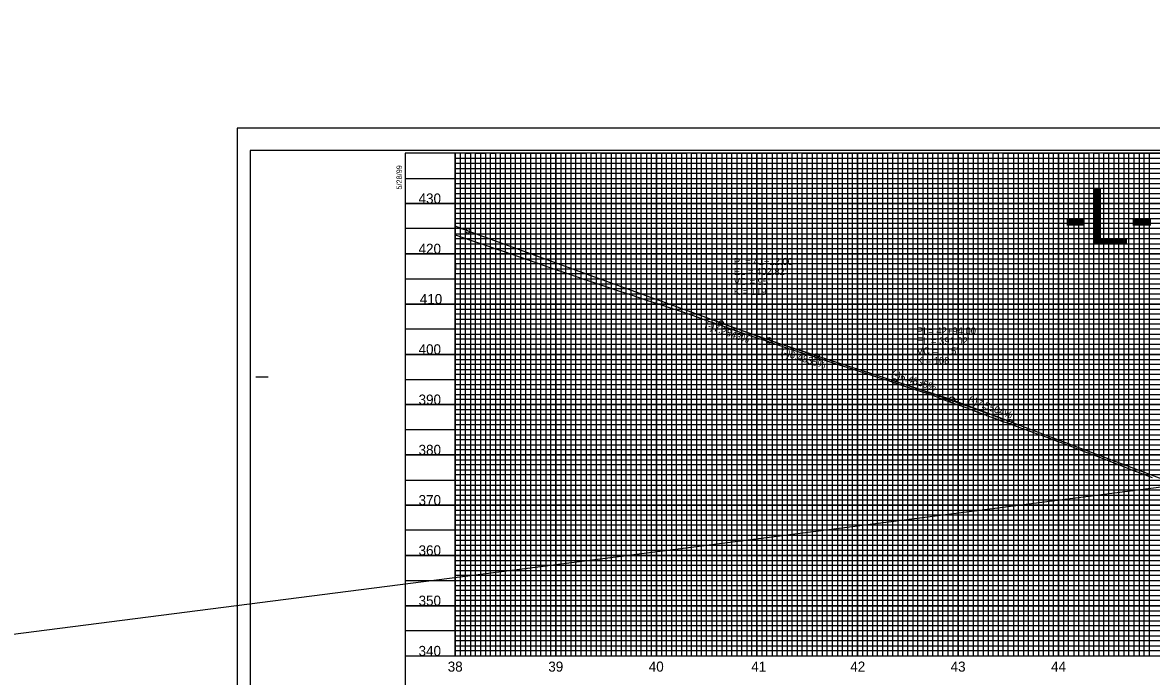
# Model space of a CAD drawing. Extents: x 571503 to 593215, y -77195 to -51828.
# Drawn here: x 583403 to 584526, y -53129 to -52479 of the extents above; entities that cross this region are included whole.
import ezdxf

# ---------------------------------------------------------------- set-up
doc = ezdxf.new("R2010")
doc.units = 0
for name, color, linetype in [('Default', 7, 'Continuous'), ('Exist Vertical Profile Ground Line', 7, 'Continuous'), ('Exist Vertical Profile Horizontal Axis Label Major', 7, 'Continuous'), ('Exist Vertical Profile Vertical Axis Label', 7, 'Continuous'), ('Prop PFL Text', 7, 'Continuous'), ('Prop Vertical Profile Curve Label', 7, 'Continuous'), ('Prop Vertical Profile Grade', 7, 'Continuous'), ('Prop Vertical Profile Grade Label', 7, 'Continuous'), ('Prop VPI Label', 7, 'Continuous'), ('Sheet Clip Boundary CELL', 7, 'Continuous'), ('Sheet DOT Grid CELL', 7, 'Continuous'), ('Sheet Plot Border Inside CELL', 7, 'Continuous'), ('Sheet Plot Border Outside CELL', 7, 'Continuous'), ('Sheet Profile CELL', 7, 'Continuous'), ('Sheet Profile Grid Major CELL', 7, 'Continuous'), ('Sheet Profile Grid Middle CELL', 7, 'Continuous'), ('Sheet Profile Grid Minor CELL', 7, 'Continuous')]:
    doc.layers.add(name, color=color, linetype=linetype)

msp = doc.modelspace()

# ---------------------------------------------------------------- linework, layer by layer
at = {"layer": 'Exist Vertical Profile Ground Line'}
for points in [[(583833.2, -52689.7), (583848.4, -52695), (583865.3, -52700.8), (583873.4, -52703.6), (583881.7, -52706.5), (583897, -52711.8), (583913.3, -52717.4), (583921.5, -52720.3), (583926.1, -52721.9), (583941.7, -52727.2), (583958.3, -52733), (583960.7, -52733.8), (583964.9, -52735.2), (583980.1, -52740.3), (583996.6, -52745.8), (584007.2, -52749.3), (584023.5, -52754.9), (584039.2, -52759.8), (584046, -52762.2), (584054.1, -52764.8), (584069.9, -52770.2), (584086.1, -52775.9), (584093.5, -52778.5), (584101, -52781.1), (584116.4, -52786.5), (584133, -52792.2), (584142.6, -52795.4), (584151.1, -52798.3), (584166.5, -52803.4), (584183.1, -52808.7), (584189.9, -52810.9), (584198.7, -52813.8), (584214.1, -52818.8), (584227.8, -52823.2), (584229.5, -52823.7), (584238.8, -52826.7), (584241, -52827.4), (584248, -52829.7), (584255, -52832), (584257.3, -52832.8), (584266.6, -52835.8), (584267.7, -52836.2), (584275.9, -52838.9), (584280.9, -52840.6), (584285.1, -52842), (584285.7, -52842.2), (584294.4, -52845.1), (584303.7, -52848.1), (584305.9, -52848.8), (584313, -52851.4), (584315.1, -52852.2), (584322.2, -52854.9)], [(584322.2, -52854.9), (584329.3, -52857.5), (584331.5, -52858.3), (584333.4, -52859), (584340.8, -52861.7), (584350.1, -52865.2), (584359.3, -52868.7), (584360.4, -52869), (584361, -52869.3), (584361.5, -52869.5), (584368.6, -52872), (584377.9, -52875.4), (584383.2, -52877.3), (584383.7, -52877.4), (584387.2, -52878.7), (584396.4, -52882), (584405.7, -52885.4), (584414.6, -52888.6), (584415, -52888.7), (584415.8, -52889), (584424.3, -52892.2), (584433.5, -52895.7), (584435.7, -52896.5), (584436.3, -52896.7), (584442.8, -52899.2), (584452.1, -52902.7), (584461.4, -52906.2), (584467.5, -52908.5), (584468, -52908.7), (584470.6, -52909.7), (584479.9, -52913.3), (584489.2, -52916.9), (584489.2, -52916.9), (584489.3, -52916.9), (584498.5, -52920.5), (584507.7, -52924.1), (584516.7, -52927.5), (584517, -52927.7), (584521.1, -52929.2), (584521.1, -52929.2), (584526.3, -52931.2)]]:
    msp.add_lwpolyline(points, dxfattribs=at)
at = {"layer": 'Prop PFL Text'}
msp.add_line((571799.6, -54572.4), (593215.4, -51828.4), dxfattribs=at)
at = {"layer": 'Prop Vertical Profile Curve Label'}
for centre in [(583845.7, -52685.8), (584097.7, -52777.5), (584192.7, -52810.2), (584269.7, -52835.2), (584384.7, -52875.6)]:
    msp.add_circle(centre, 2.25, dxfattribs=at)
at = {"layer": 'Prop Vertical Profile Grade'}
for p, q in [((583845.7, -52685.8), (584097.7, -52777.5)), ((584192.7, -52810.2), (584269.7, -52835.2)), ((584384.7, -52875.6), (584642.2, -52972.8))]:
    msp.add_line(p, q, dxfattribs=at)
for points in [[(583833.2, -52681.3), (583837, -52682.6), (583845.7, -52685.8)], [(584097.7, -52777.5), (584099.6, -52778.2), (584101.5, -52778.9), (584103.4, -52779.6), (584105.3, -52780.3), (584107.2, -52781), (584109.1, -52781.7), (584111, -52782.4), (584112.9, -52783), (584114.8, -52783.7), (584116.7, -52784.4), (584118.6, -52785.1), (584120.5, -52785.7), (584122.4, -52786.4), (584124.3, -52787.1), (584126.2, -52787.8), (584128.1, -52788.4), (584130, -52789.1), (584131.9, -52789.8), (584133.8, -52790.4), (584135.7, -52791.1), (584137.6, -52791.7), (584139.5, -52792.4), (584141.4, -52793.1), (584143.3, -52793.7), (584145.2, -52794.4), (584147.1, -52795), (584149, -52795.7), (584150.9, -52796.3), (584152.8, -52797), (584154.7, -52797.6), (584156.6, -52798.3), (584158.5, -52798.9), (584160.4, -52799.6), (584162.3, -52800.2), (584164.2, -52800.8), (584166.1, -52801.5), (584168, -52802.1), (584169.9, -52802.7), (584171.8, -52803.4), (584173.7, -52804), (584175.6, -52804.6), (584177.5, -52805.3), (584179.4, -52805.9), (584181.3, -52806.5), (584183.2, -52807.1), (584185.1, -52807.8), (584187, -52808.4), (584188.9, -52809), (584190.8, -52809.6), (584192.7, -52810.2)], [(584269.7, -52835.2), (584272, -52836), (584274.3, -52836.7), (584276.6, -52837.5), (584278.9, -52838.2), (584281.2, -52839), (584283.5, -52839.7), (584285.8, -52840.5), (584288.1, -52841.3), (584290.4, -52842), (584292.7, -52842.8), (584295, -52843.6), (584297.3, -52844.3), (584299.6, -52845.1), (584301.9, -52845.9), (584304.2, -52846.7), (584306.5, -52847.5), (584308.8, -52848.2), (584311.1, -52849), (584313.4, -52849.8), (584315.7, -52850.6), (584318, -52851.4), (584320.3, -52852.2), (584322.6, -52853), (584324.9, -52853.8), (584327.2, -52854.6), (584329.5, -52855.4), (584331.8, -52856.2), (584334.1, -52857), (584336.4, -52857.9), (584338.7, -52858.7), (584341, -52859.5), (584343.3, -52860.3), (584345.6, -52861.2), (584347.9, -52862), (584350.2, -52862.8), (584352.5, -52863.6), (584354.8, -52864.5), (584357.1, -52865.3), (584359.4, -52866.2), (584361.7, -52867), (584364, -52867.8), (584366.3, -52868.7), (584368.6, -52869.5), (584370.9, -52870.4), (584373.2, -52871.2), (584375.5, -52872.1), (584377.8, -52873), (584380.1, -52873.8), (584382.4, -52874.7), (584384.7, -52875.6)]]:
    msp.add_spline(points, degree=3, dxfattribs=at)
at = {"layer": 'Prop VPI Label'}
for p, q in [((583845.7, -52685.8), (583833.2, -52681.2)), ((584097.7, -52777.5), (584142.6, -52793.9)), ((584192.7, -52810.2), (584147.8, -52795.7)), ((584269.7, -52835.2), (584324.6, -52853)), ((584384.7, -52875.6), (584329.8, -52854.8))]:
    msp.add_line(p, q, dxfattribs=at)
for centre in [(584145.2, -52794.8), (584327.2, -52853.8)]:
    msp.add_circle(centre, 2.75, dxfattribs=at)
at = {"layer": 'Sheet Clip Boundary CELL'}
msp.add_lwpolyline([(583833.2, -52608.7), (583833.2, -53108.7), (585233.2, -53108.7), (585233.2, -52746.2), (585083.2, -52746.2), (585083.2, -52608.7)], close=True, dxfattribs=at)
at = {"layer": 'Sheet DOT Grid CELL'}
for p, q in [((583833.2, -53108.7), (583833.2, -52608.7)), ((583833.2, -53108.7), (583833.2, -52608.7)), ((583883.2, -53108.7), (583883.2, -52608.7)), ((583883.2, -53108.7), (583883.2, -52608.7)), ((583933.2, -53108.7), (583933.2, -52608.7)), ((583933.2, -53108.7), (583933.2, -52608.7)), ((583983.2, -53108.7), (583983.2, -52608.7)), ((583983.2, -53108.7), (583983.2, -52608.7)), ((584033.2, -53108.7), (584033.2, -52608.7)), ((584033.2, -53108.7), (584033.2, -52608.7)), ((584083.2, -53108.7), (584083.2, -52608.7)), ((584083.2, -53108.7), (584083.2, -52608.7)), ((584133.2, -53108.7), (584133.2, -52608.7)), ((584133.2, -53108.7), (584133.2, -52608.7)), ((584183.2, -53108.7), (584183.2, -52608.7)), ((584183.2, -53108.7), (584183.2, -52608.7)), ((584233.2, -53108.7), (584233.2, -52608.7)), ((584233.2, -53108.7), (584233.2, -52608.7)), ((584283.2, -53108.7), (584283.2, -52608.7)), ((584283.2, -53108.7), (584283.2, -52608.7)), ((584333.2, -53108.7), (584333.2, -52608.7)), ((584333.2, -53108.7), (584333.2, -52608.7)), ((584383.2, -53108.7), (584383.2, -52608.7)), ((584383.2, -53108.7), (584383.2, -52608.7)), ((584433.2, -53108.7), (584433.2, -52608.7)), ((584433.2, -53108.7), (584433.2, -52608.7)), ((584483.2, -53108.7), (584483.2, -52608.7)), ((584483.2, -53108.7), (584483.2, -52608.7)), ((583783.2, -52658.7), (585083.2, -52658.7)), ((585083.2, -52658.7), (583783.2, -52658.7)), ((583783.2, -52708.7), (585083.2, -52708.7)), ((585083.2, -52708.7), (583783.2, -52708.7)), ((583783.2, -52758.7), (585283.2, -52758.7)), ((585283.2, -52758.7), (583783.2, -52758.7)), ((583783.2, -52808.7), (585283.2, -52808.7)), ((585283.2, -52808.7), (583783.2, -52808.7)), ((583783.2, -52858.7), (585283.2, -52858.7)), ((585283.2, -52858.7), (583783.2, -52858.7)), ((583783.2, -52908.7), (585283.2, -52908.7)), ((585283.2, -52908.7), (583783.2, -52908.7)), ((583783.2, -52958.7), (585283.2, -52958.7)), ((585283.2, -52958.7), (583783.2, -52958.7)), ((583783.2, -53008.7), (585283.2, -53008.7)), ((585283.2, -53008.7), (583783.2, -53008.7)), ((583783.2, -53058.7), (585283.2, -53058.7)), ((585283.2, -53058.7), (583783.2, -53058.7))]:
    msp.add_line(p, q, dxfattribs=at)
at = {"layer": 'Sheet Plot Border Inside CELL'}
msp.add_lwpolyline([(583629.2, -53661.2), (585295.7, -53661.2), (585295.7, -52606.1), (583629.2, -52606.1)], close=True, dxfattribs=at)
at = {"layer": 'Sheet Plot Border Outside CELL'}
msp.add_lwpolyline([(583616.2, -53683.7), (585300.2, -53683.7), (585300.2, -52583.7), (583616.2, -52583.7)], close=True, dxfattribs=at)
at = {"layer": 'Sheet Profile CELL'}
for p, q in [((585300.2, -52583.7), (583616.2, -52583.7)), ((583616.2, -52583.7), (583616.2, -53683.7)), ((583634.7, -52831.2), (583647.2, -52831.2)), ((583783.2, -53108.7), (585283.2, -53108.7))]:
    msp.add_line(p, q, dxfattribs=at)
msp.add_lwpolyline([(585283.2, -52608.7), (583783.2, -52608.7), (583783.2, -53658.7), (585283.2, -53658.7)], close=True, dxfattribs=at)
at = {"layer": 'Sheet Profile Grid Major CELL'}
for points in [[(583833.2, -52608.7), (583833.2, -53108.7), (583883.2, -53108.7), (583883.2, -52608.7), (583933.2, -52608.7), (583933.2, -53108.7), (583983.2, -53108.7), (583983.2, -52608.7), (584033.2, -52608.7), (584033.2, -53108.7), (584083.2, -53108.7), (584083.2, -52608.7), (584133.2, -52608.7), (584133.2, -53108.7), (584183.2, -53108.7), (584183.2, -52608.7), (584233.2, -52608.7), (584233.2, -53108.7), (584283.2, -53108.7), (584283.2, -52608.7), (584333.2, -52608.7), (584333.2, -53108.7), (584383.2, -53108.7), (584383.2, -52608.7), (584433.2, -52608.7), (584433.2, -53108.7), (584483.2, -53108.7), (584483.2, -52608.7), (584533.2, -52608.7)], [(583783.2, -52658.7), (585083.2, -52658.7)], [(585083.2, -52708.7), (583783.2, -52708.7), (583783.2, -52758.7), (585283.2, -52758.7)], [(585283.2, -52808.7), (583783.2, -52808.7), (583783.2, -52858.7), (585283.2, -52858.7)], [(585283.2, -52908.7), (583783.2, -52908.7), (583783.2, -52958.7), (585283.2, -52958.7)], [(585283.2, -53008.7), (583783.2, -53008.7), (583783.2, -53008.7), (583783.2, -53058.7), (585283.2, -53058.7)]]:
    msp.add_lwpolyline(points, dxfattribs=at)
at = {"layer": 'Sheet Profile Grid Middle CELL'}
msp.add_line((583783.2, -52633.7), (585083.2, -52633.7), dxfattribs=at)
for points in [[(583858.2, -52608.7), (583858.2, -53108.7), (583908.2, -53108.7), (583908.2, -52608.7), (583958.2, -52608.7), (583958.2, -53108.7), (584008.2, -53108.7), (584008.2, -52608.7), (584058.2, -52608.7), (584058.2, -53108.7), (584108.2, -53108.7), (584108.2, -52608.7), (584158.2, -52608.7), (584158.2, -53108.7), (584208.2, -53108.7), (584208.2, -52608.7), (584258.2, -52608.7), (584258.2, -53108.7), (584308.2, -53108.7), (584308.2, -52608.7), (584358.2, -52608.7), (584358.2, -53108.7), (584408.2, -53108.7), (584408.2, -53108.7), (584408.2, -52608.7), (584458.2, -52608.7), (584458.2, -53108.7), (584508.2, -53108.7), (584508.2, -52608.7), (584558.2, -52608.7)], [(585083.2, -52683.7), (583783.2, -52683.7), (583783.2, -52733.7), (585083.2, -52733.7)], [(585283.2, -52783.7), (583783.2, -52783.7), (583783.2, -52833.7), (585108.2, -52833.7)], [(585283.2, -52883.7), (583783.2, -52883.7), (583783.2, -52933.7), (585283.2, -52933.7)], [(585283.2, -52983.7), (583783.2, -52983.7), (583783.2, -53033.7), (585283.2, -53033.7)], [(585283.2, -53083.7), (583783.2, -53083.7)]]:
    msp.add_lwpolyline(points, dxfattribs=at)
at = {"layer": 'Sheet Profile Grid Minor CELL'}
for p, q in [((583833.2, -52613.7), (585083.2, -52613.7)), ((583833.2, -52618.7), (583833.2, -52618.7)), ((585083.2, -52618.7), (583833.2, -52619)), ((583833.2, -52623.7), (585083.2, -52623.7)), ((585083.2, -52743.7), (583833.2, -52743.7)), ((585233.2, -52748.7), (583833.2, -52748.7)), ((585233.2, -52753.7), (583833.2, -52753.7)), ((583833.2, -52763.7), (585233.2, -52763.7)), ((585233.2, -52768.7), (583833.2, -52768.7)), ((583833.2, -52773.7), (585233.2, -52773.7)), ((585233.2, -52793.7), (583833.2, -52793.7)), ((583833.2, -52798.7), (585233.2, -52798.7)), ((585233.2, -52818.7), (583833.2, -52818.7)), ((583833.2, -52823.7), (585233.2, -52823.7)), ((585233.2, -52843.7), (583833.2, -52843.7)), ((583833.2, -52848.7), (585233.2, -52848.7)), ((585233.2, -52853.7), (583833.2, -52853.7)), ((583833.2, -52863.7), (585233.2, -52863.7)), ((585233.2, -52868.7), (583833.2, -52868.7)), ((583833.2, -52873.7), (585233.2, -52873.7)), ((585233.2, -52878.7), (583833.2, -52878.7)), ((583833.2, -52888.7), (585233.2, -52888.7)), ((585233.2, -52893.7), (583833.2, -52893.7)), ((583833.2, -52898.7), (585233.2, -52898.7)), ((585233.2, -52903.7), (583833.2, -52903.7)), ((583833.2, -52913.7), (585233.2, -52913.7)), ((585233.2, -52918.7), (583833.2, -52918.7)), ((583833.2, -52923.7), (585233.2, -52923.7)), ((585233.2, -52928.7), (583833.2, -52928.7)), ((583833.2, -52938.7), (585233.2, -52938.7)), ((585233.2, -52943.7), (583833.2, -52943.7)), ((583833.2, -52948.7), (585233.2, -52948.7)), ((585233.2, -52953.7), (583833.2, -52953.7)), ((583833.2, -52963.7), (585233.2, -52963.7)), ((585233.2, -52968.7), (583833.2, -52968.7)), ((583833.2, -52973.7), (585233.2, -52973.7)), ((585233.2, -52978.7), (583833.2, -52978.7)), ((583833.2, -52988.7), (585233.2, -52988.7)), ((585233.2, -52993.7), (583833.2, -52993.7)), ((585233.2, -52998.7), (583833.2, -52998.7)), ((585233.2, -53003.7), (583833.2, -53003.7)), ((583833.2, -53013.7), (585233.2, -53013.7)), ((585233.2, -53018.7), (583833.2, -53018.7)), ((583833.2, -53023.7), (585233.2, -53023.7)), ((585233.2, -53028.7), (583833.2, -53028.7)), ((583833.2, -53038.7), (585233.2, -53038.7)), ((585233.2, -53043.7), (583833.2, -53043.7)), ((583833.2, -53048.7), (585233.2, -53048.7)), ((585233.2, -53053.7), (583833.2, -53053.7)), ((583833.2, -53063.7), (585233.2, -53063.7)), ((585233.2, -53068.7), (583833.2, -53068.7)), ((583833.2, -53073.7), (585233.2, -53073.7)), ((585233.2, -53078.7), (583833.2, -53078.7)), ((583833.2, -53088.7), (585233.2, -53088.7)), ((585233.2, -53093.7), (583833.2, -53093.7)), ((583833.2, -53098.7), (585233.2, -53098.7))]:
    msp.add_line(p, q, dxfattribs=at)
for points in [[(583838.2, -52608.7), (583838.2, -53108.7), (583843.2, -53108.7), (583843.2, -52608.7), (583848.2, -52608.7), (583848.2, -53108.7), (583853.2, -53108.7), (583853.2, -52608.7), (583863.2, -52608.7), (583863.2, -53108.7), (583868.2, -53108.7), (583868.2, -52608.7), (583873.2, -52608.7), (583873.2, -53108.7), (583878.2, -53108.7), (583888.2, -53108.7), (583893.2, -53108.7), (583893.2, -52608.7), (583898.2, -52608.7), (583898.2, -53108.7), (583903.2, -53108.7), (583903.2, -52608.7), (583913.2, -52608.7), (583913.2, -53108.7), (583918.2, -53108.7), (583918.2, -52608.7), (583923.2, -52608.7), (583923.2, -53108.7), (583928.2, -53108.7), (583928.2, -52608.7), (583938.2, -52608.7), (583938.2, -53108.7), (583943.2, -53108.7), (583943.2, -52608.7), (583948.2, -52608.7), (583948.2, -53108.7), (583953.2, -53108.7), (583953.2, -52608.7), (583963.2, -52608.7), (583963.2, -53108.7), (583968.2, -53108.7), (583968.2, -52608.7), (583973.2, -52608.7), (583973.2, -53108.7), (583978.2, -53108.7), (583978.2, -52608.7), (583988.2, -52608.7), (583988.2, -53108.7), (583993.2, -53108.7), (583993.2, -52608.7), (583998.2, -52608.7), (583998.2, -53108.7), (584003.2, -53108.7), (584003.2, -52608.7), (584013.2, -52608.7), (584013.2, -53108.7), (584018.2, -53108.7), (584018.2, -52608.7), (584023.2, -52608.7), (584023.2, -53108.7), (584028.2, -53108.7), (584028.2, -52608.7), (584038.2, -52608.7), (584038.2, -53108.7), (584043.2, -53108.7), (584043.2, -52608.7), (584048.2, -52608.7), (584048.2, -53108.7)], [(583878.2, -53108.7), (583878.2, -52608.7), (583888.2, -52608.7), (583888.2, -53108.7)], [(584048.2, -53108.7), (584053.2, -53108.7), (584053.2, -52608.7), (584063.2, -52608.7), (584063.2, -53108.7), (584068.2, -53108.7), (584068.2, -52608.7), (584073.2, -52608.7), (584073.2, -53108.7), (584078.2, -53108.7), (584078.2, -52608.7), (584088.2, -52608.7), (584088.2, -53108.7), (584093.2, -53108.7), (584093.2, -52608.7), (584098.2, -52608.7), (584098.2, -53108.7), (584103.2, -53108.7), (584103.2, -52608.7), (584113.2, -52608.7), (584113.2, -53108.7), (584118.2, -53108.7), (584118.2, -52608.7), (584123.2, -52608.7), (584123.2, -53108.7), (584128.2, -53108.7), (584128.2, -52608.7), (584138.2, -52608.7), (584138.2, -53108.7), (584143.2, -53108.7), (584143.2, -52608.7), (584148.2, -52608.7), (584148.2, -53108.7), (584153.2, -53108.7), (584153.2, -52608.7), (584163.2, -52608.7), (584163.2, -53108.7), (584168.2, -53108.7), (584168.2, -52608.7), (584173.2, -52608.7), (584173.2, -53108.7), (584178.2, -53108.7), (584178.2, -52608.7), (584188.2, -52608.7), (584188.2, -53108.7), (584193.2, -53108.7), (584193.2, -52608.7), (584198.2, -52608.7), (584198.2, -53108.7), (584203.2, -53108.7), (584203.2, -52608.7), (584213.2, -52608.7), (584213.2, -53108.7), (584218.2, -53108.7), (584218.2, -52608.7), (584223.2, -52608.7), (584223.2, -53108.7), (584228.2, -53108.7), (584228.2, -52608.7), (584238.2, -52608.7), (584238.2, -53108.7), (584243.2, -53108.7), (584243.2, -52608.7), (584248.2, -52608.7), (584248.2, -53108.7), (584253.2, -53108.7), (584253.2, -52608.7), (584263.2, -52608.7), (584263.2, -53108.7), (584268.2, -53108.7), (584268.2, -52608.7), (584273.2, -52608.7), (584273.2, -53108.7), (584278.2, -53108.7), (584278.2, -52608.7), (584288.2, -52608.7), (584288.2, -53108.7), (584293.2, -53108.7), (584293.2, -52608.7), (584298.2, -52608.7), (584298.2, -53108.7), (584303.2, -53108.7), (584303.2, -52608.7), (584313.2, -52608.7), (584313.2, -53108.7), (584318.2, -53108.7), (584318.2, -52608.7), (584323.2, -52608.7), (584323.2, -53108.7), (584328.2, -53108.7), (584328.2, -52608.7), (584338.2, -52608.7), (584338.2, -53108.7), (584343.2, -53108.7), (584343.2, -52608.7), (584348.2, -52608.7), (584348.2, -53108.7), (584353.2, -53108.7), (584353.2, -52608.7), (584363.2, -52608.7)], [(584363.2, -52608.7), (584363.2, -53108.7), (584368.2, -53108.7), (584368.2, -52608.7), (584373.2, -52608.7), (584373.2, -53108.7), (584378.2, -53108.7), (584378.2, -52608.7), (584388.2, -52608.7), (584388.2, -53108.7), (584393.2, -53108.7), (584393.2, -52608.7), (584398.2, -52608.7), (584398.2, -53108.7), (584403.2, -53108.7), (584403.2, -52608.7), (584413.2, -52608.7), (584413.2, -53108.7), (584418.2, -53108.7), (584418.2, -52608.7), (584423.2, -52608.7), (584423.2, -53108.7), (584428.2, -53108.7), (584428.2, -52608.7), (584438.2, -52608.7), (584438.2, -53108.7), (584443.2, -53108.7), (584443.2, -52608.7), (584448.2, -52608.7), (584448.2, -53108.7), (584453.2, -53108.7), (584453.2, -52608.7), (584463.2, -52608.7), (584463.2, -53108.7), (584468.2, -53108.7), (584468.2, -52608.7), (584473.2, -52608.7), (584473.2, -53108.7), (584478.2, -53108.7), (584478.2, -52608.7), (584488.2, -52608.7), (584488.2, -53108.7), (584488.2, -53108.7), (584493.2, -53108.7), (584493.2, -52608.7), (584498.2, -52608.7), (584498.2, -53108.7), (584503.2, -53108.7), (584503.2, -52608.7), (584513.2, -52608.7), (584513.2, -53108.7), (584518.2, -53108.7), (584518.2, -52608.7), (584523.2, -52608.7), (584523.2, -53108.7), (584528.2, -53108.7)], [(585083.2, -52628.7), (583833.2, -52628.7), (583833.2, -52638.7), (585083.2, -52638.7)], [(585083.2, -52643.7), (583833.2, -52643.7), (583833.2, -52648.7), (585083.2, -52648.7)], [(585083.2, -52653.7), (583833.2, -52653.7), (583833.2, -52663.7), (585083.2, -52663.7)], [(585083.2, -52668.7), (583833.2, -52668.7), (583833.2, -52673.7), (585083.2, -52673.7)], [(585083.2, -52678.7), (583833.2, -52678.7), (583833.2, -52688.7), (585083.2, -52688.7)], [(585083.2, -52693.7), (583833.2, -52693.7), (583833.2, -52698.7), (585083.2, -52698.7)], [(585083.2, -52703.7), (583833.2, -52703.7), (583833.2, -52713.7), (585083.2, -52713.7)], [(585083.2, -52718.8), (583833.3, -52718.8), (583833.3, -52723.7), (585083.2, -52723.7)], [(585083.2, -52728.7), (583833.2, -52728.7), (583833.2, -52738.7), (585083.2, -52738.7)], [(585233.2, -52778.7), (583833.2, -52778.7), (583833.2, -52788.7), (585233.2, -52788.7)], [(585233.2, -52803.7), (583833.2, -52803.7), (583833.2, -52813.7), (585233.2, -52813.7)], [(585233.2, -52828.7), (583833.2, -52828.7), (583833.2, -52838.7), (585233.2, -52838.7)], [(585233.2, -53103.7), (583833.2, -53103.7)]]:
    msp.add_lwpolyline(points, dxfattribs=at)

# ---------------------------------------------------------------- texts
at = {"layer": 'Default'}
msp.add_text('-L-', height=55.36, dxfattribs=at).set_placement((584437.8, -52699))
at = {"layer": 'Exist Vertical Profile Horizontal Axis Label Major'}
for s, p in [('38', (583825.7, -53124.3)), ('39', (583925.7, -53124.3)), ('40', (584025.6, -53124.3)), ('41', (584127.5, -53124.3)), ('42', (584226, -53124.3)), ('43', (584325.8, -53124.3)), ('44', (584425.7, -53124.3))]:
    msp.add_text(s, height=10, dxfattribs=at).set_placement(p)
at = {"layer": 'Exist Vertical Profile Vertical Axis Label'}
for s, p in [('430', (583796.7, -52658.7)), ('420', (583796.7, -52708.7)), ('410', (583797.9, -52758.7)), ('410', (583797.9, -52758.7)), ('400', (583796.7, -52808.7)), ('400', (583796.7, -52808.7)), ('390', (583796.7, -52858.7)), ('390', (583796.7, -52858.7)), ('380', (583796.7, -52908.7)), ('380', (583796.7, -52908.7)), ('370', (583796.7, -52958.7)), ('370', (583796.7, -52958.7)), ('360', (583796.7, -53008.7)), ('360', (583796.7, -53008.7)), ('350', (583796.7, -53058.7)), ('350', (583796.7, -53058.7)), ('340', (583796.7, -53108.7)), ('340', (583796.7, -53108.7))]:
    msp.add_text(s, height=10, dxfattribs=at).set_placement(p)
at = {"layer": 'Prop Vertical Profile Curve Label'}
for s, p in [("VC = 95'", (584110.2, -52739.8)), ('K = 119', (584110.2, -52749.7)), ("VC = 115'", (584292.2, -52808.8)), ('K = 108', (584292.2, -52818.4))]:
    msp.add_text(s, height=7, dxfattribs=at).set_placement(p)
at = {"layer": 'Prop Vertical Profile Grade Label'}
for s, rotation, p in [('(-)7.2843%', 339.9875, (584080.7, -52782)), ('(-)6.4835%', 342.0386, (584156.3, -52808.9)), ('(-)6.4835%', 342.0386, (584266.2, -52830.9)), ('(-)7.5504%', 339.3174, (584342.5, -52856.4))]:
    msp.add_text(s, height=7, rotation=rotation, dxfattribs=at).set_placement(p)
at = {"layer": 'Prop VPI Label'}
for s, p in [('PI = 41+12.00', (584110.2, -52719.8)), ("EL = 402.82'", (584110.2, -52729.8)), ('PI = 42+94.00', (584292.2, -52788.8)), ("EL = 391.02'", (584292.2, -52798.8))]:
    msp.add_text(s, height=7, dxfattribs=at).set_placement(p)
at = {"layer": 'Sheet Profile CELL'}
msp.add_text('5/28/99', height=5.25, rotation=90, dxfattribs=at).set_placement((583780, -52644.8))

doc.saveas('drawing.dxf')
